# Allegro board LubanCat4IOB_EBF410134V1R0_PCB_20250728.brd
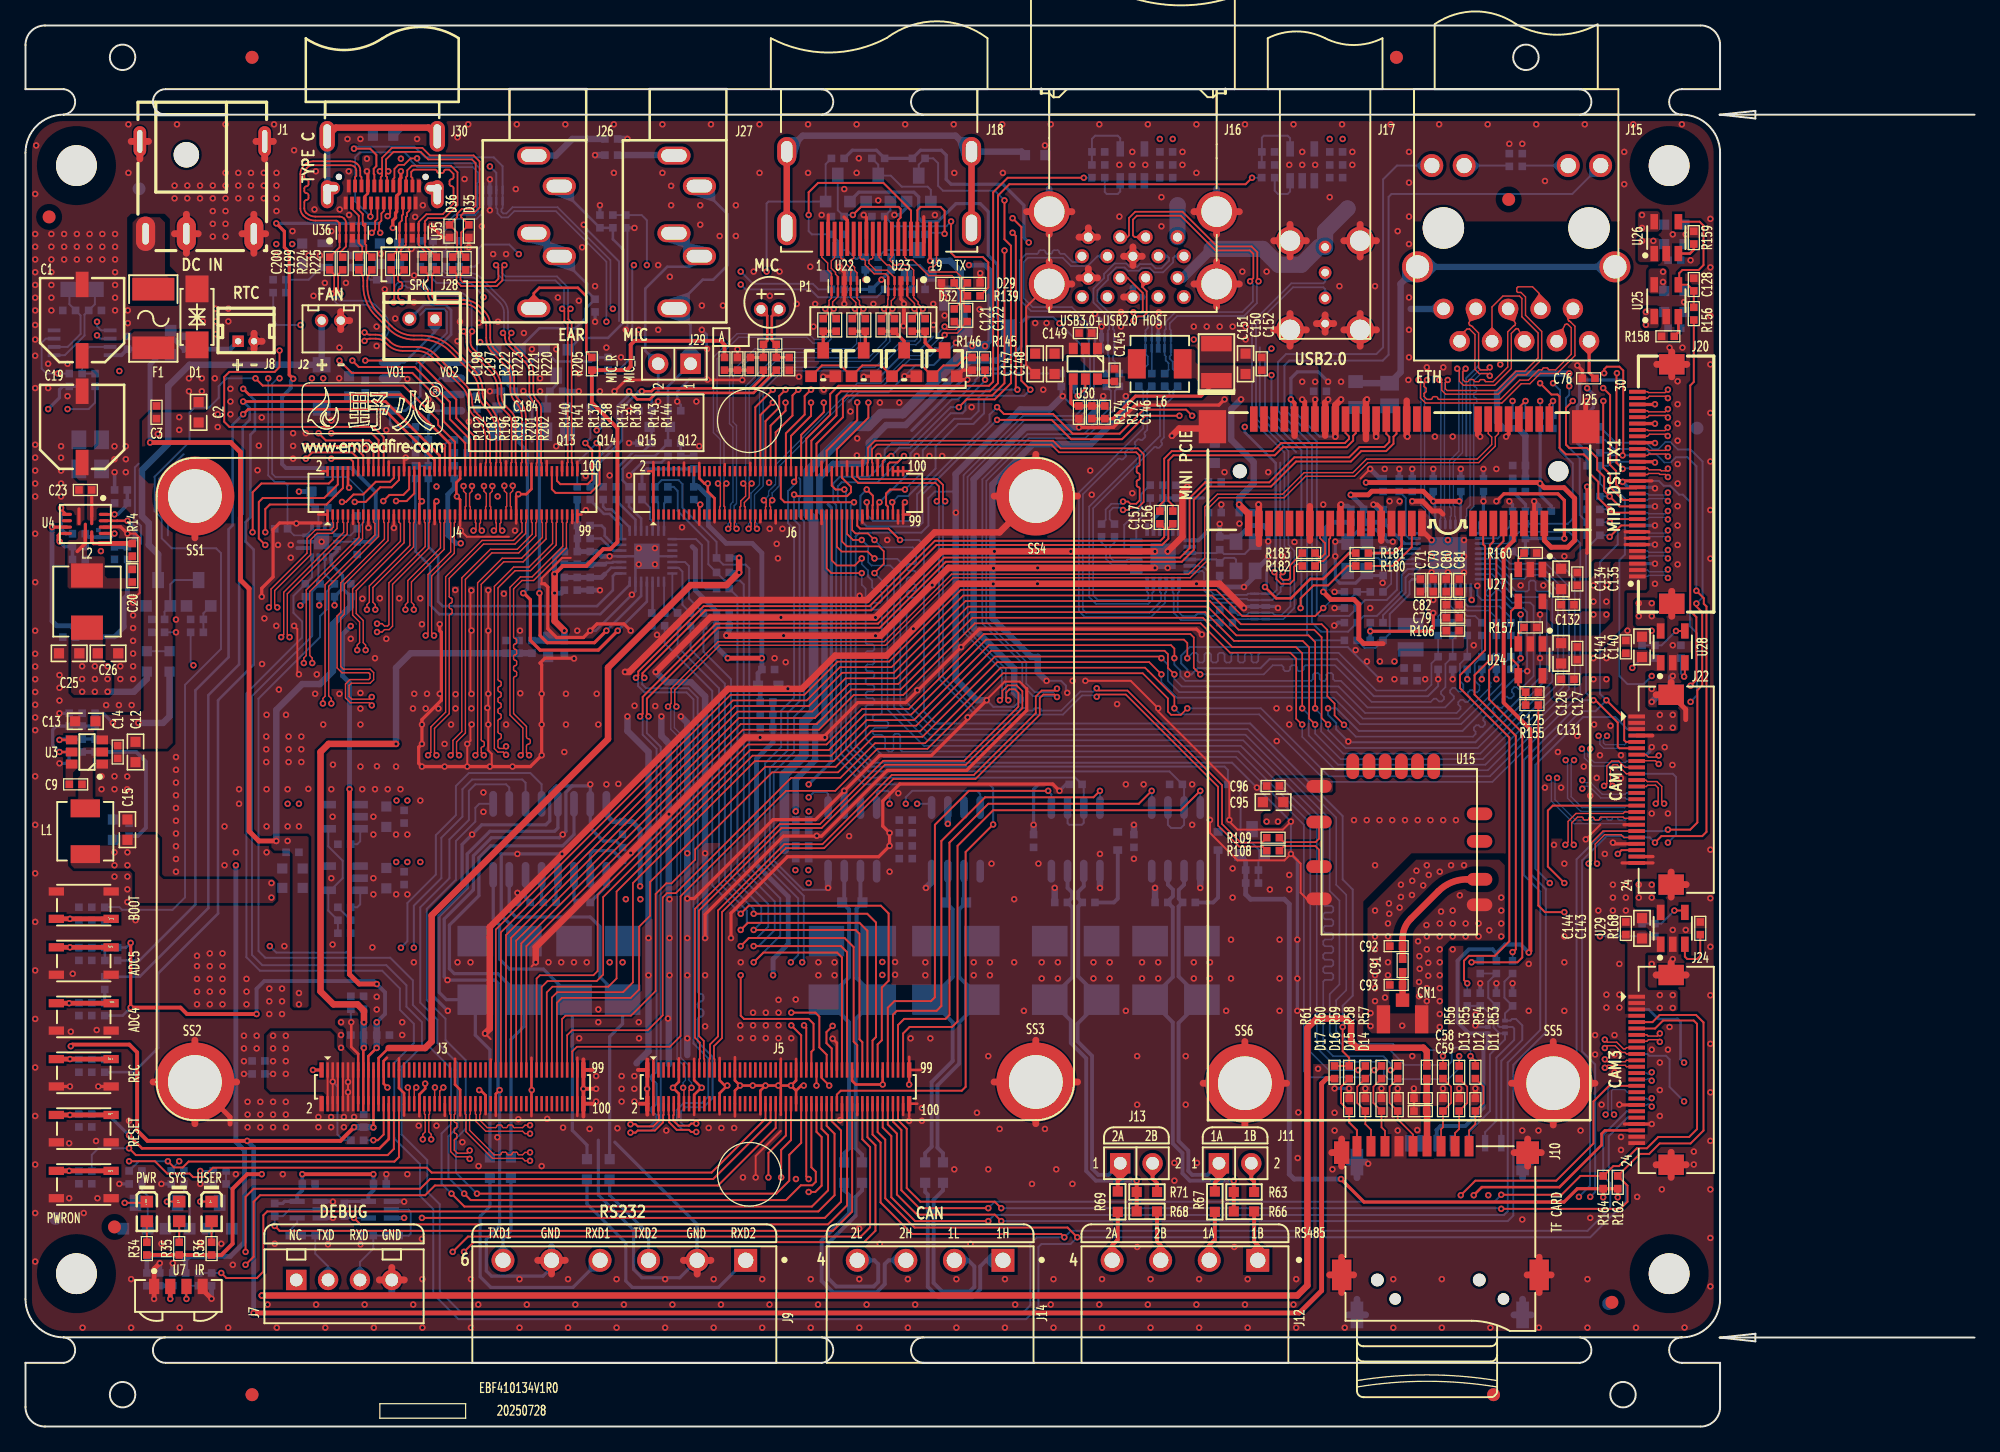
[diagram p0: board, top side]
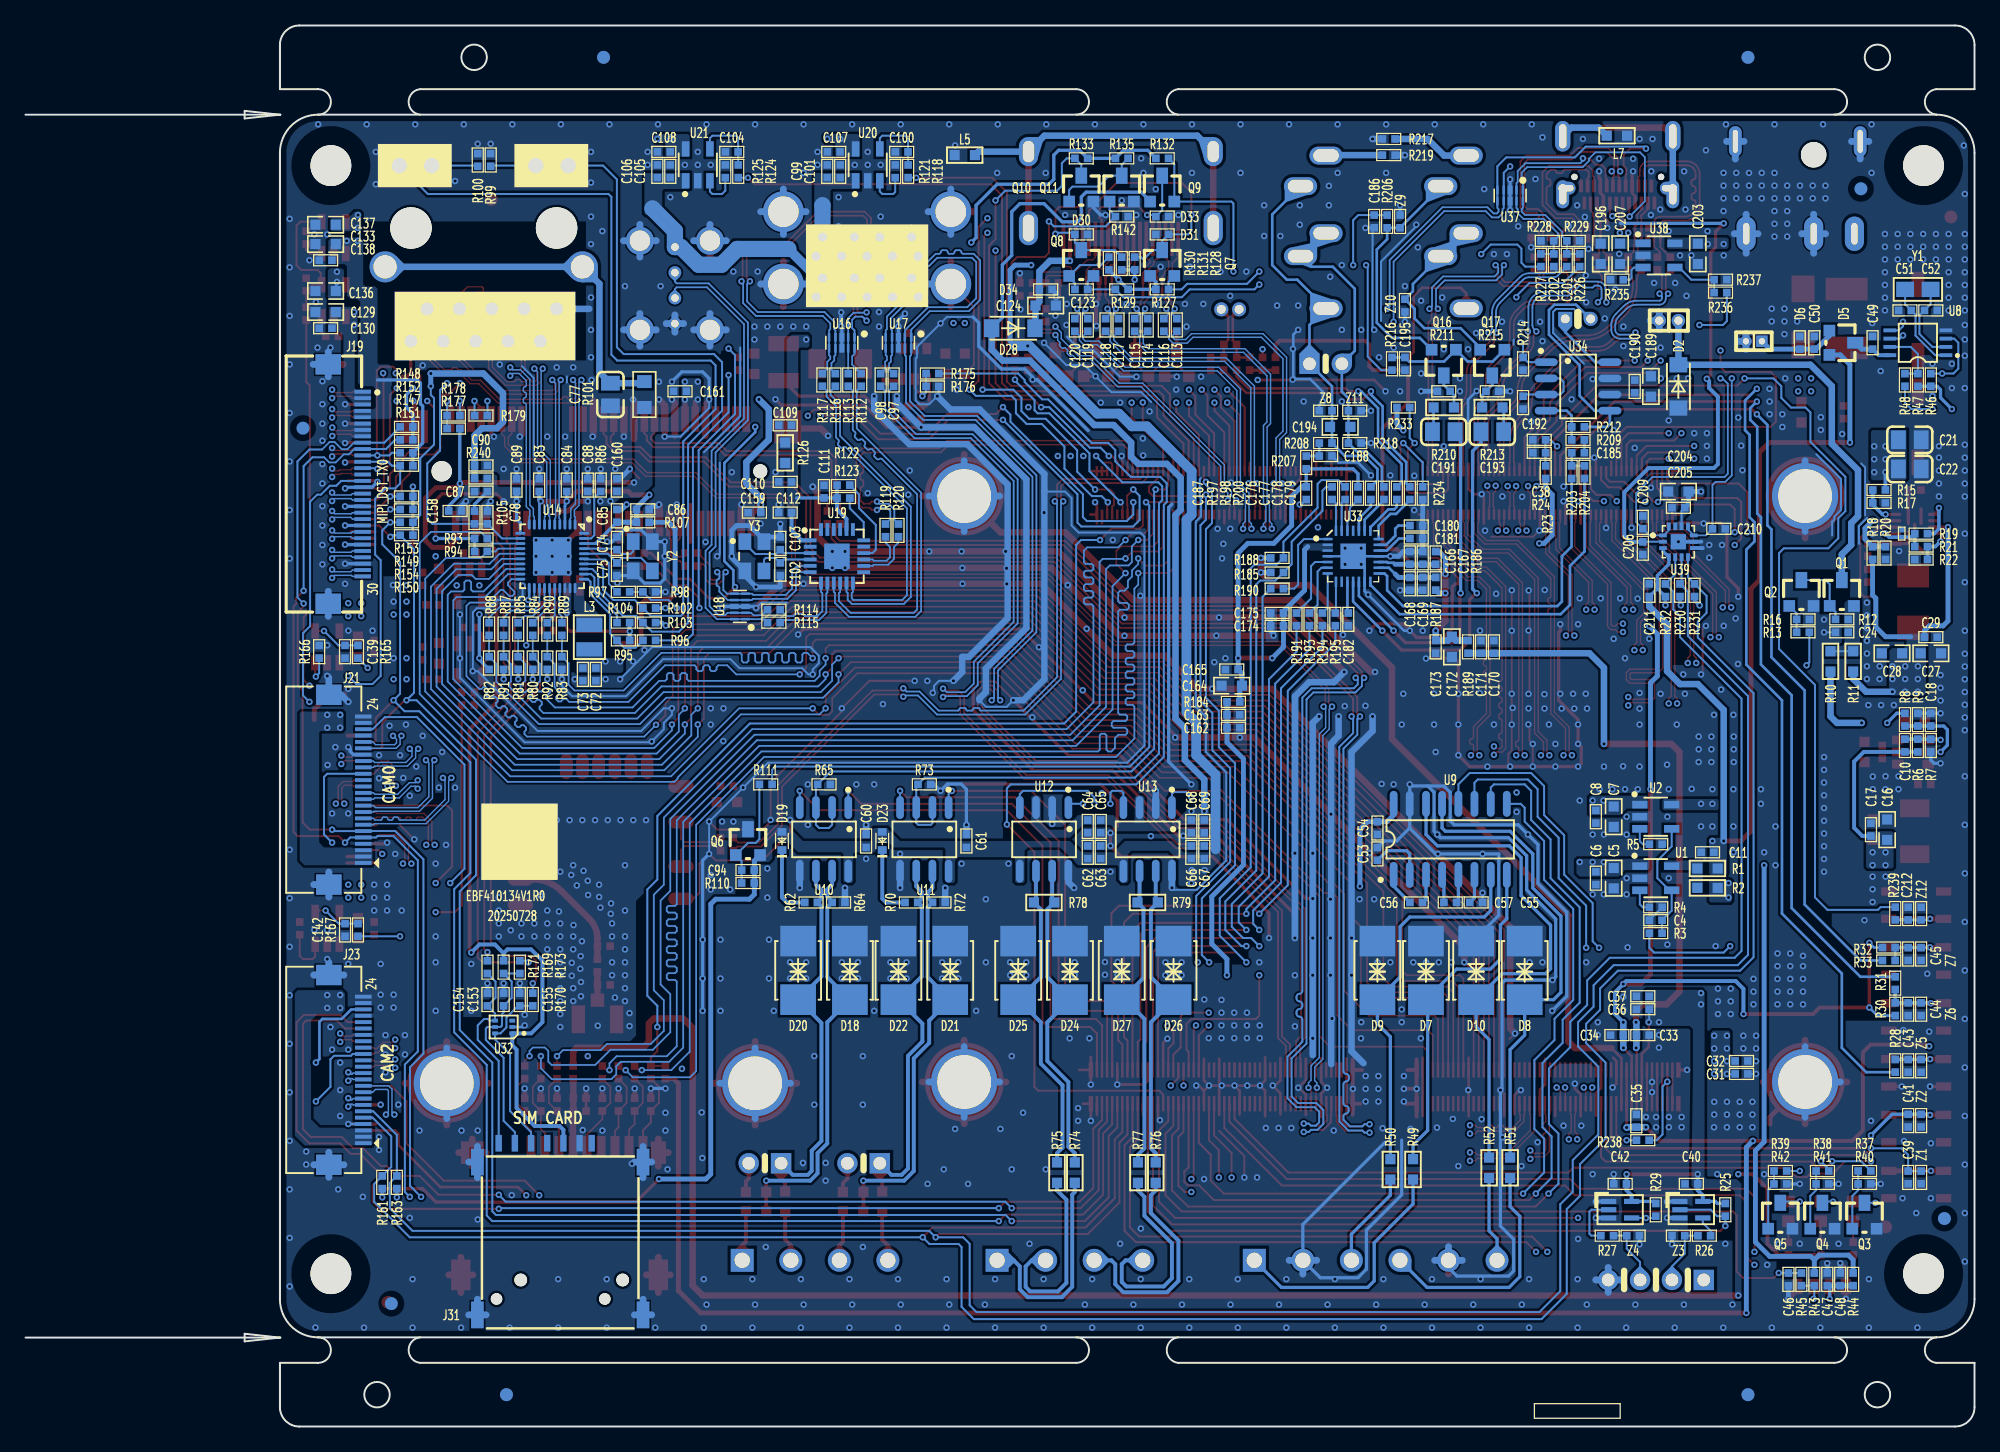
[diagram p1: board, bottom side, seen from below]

Outline 152.97 x 110 mm; copper layers: TOP, GND02, ART03, PWR04, GND05, BOTTOM. Coordinates in mm from the lower left corner of the outline.
Outline path: circle c7.62,107.5 r1 ; circle c7.62,2.5 r1 ; circle c117.76,107.5 r1 ; circle c125.38,2.5 r1 ; 3,105 0,105 0,108.48 arc(0.45,109.55) 1.52,110 131.48,110 arc(132.55,109.55) 133,108.48 133,105 130,105 ; 3,5 0,5 0,1.52 arc(0.45,0.45) 1.52,0 131.48,0 arc(132.55,0.45) 133,1.52 133,5 130,5 ; 11,105 62.5,105 ; 11,5 62.5,5 ; 70.5,105 122,105 ; 70.5,5 122,5 ; 0,100 arc(0.88,102.12) 3,103 130,103 arc(132.12,102.12) 133,100 133,10 arc(132.12,7.88) 130,7 3,7 arc(0.88,7.88) 0,10 0,100

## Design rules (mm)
net group 50OHM: nets GMAC1_MDC GMAC1_MDIO
net group B_DM1: nets B_DM1 HUB_DM1
net group B_DM2: nets B_DM2 HUB_DM2
net group B_DM3: nets B_DM3 HUB_DM3
net group B_DP1: nets B_DP1 HUB_DP1
net group B_DP2: nets B_DP2 HUB_DP2
net group B_DP3: nets B_DP3 HUB_DP3
net group C_GMAC1_TX: nets GMAC1_TXCLK GMAC1_TXEN
net group DIFF85OHM: nets PCIE20_0_RXN PCIE20_0_RXP
net group DIFF90OHM: nets USB30_SSRXN USB30_SSRXP
net group DIFF_TYPEC_CC: nets TYPEC_CC1 TYPEC_CC2
net group GMAC1_INT: nets GMAC1_INT N15600826
net group GMAC1_MCLK_INOUT: nets GMAC1_MCLK_INOUT PHY1_CLKOUT125
net group GMAC1_RXCLK: nets GMAC1_RXCLK N15599549
net group GMAC1_RXD0: nets GMAC1_RXD0 N15599533
net group GMAC1_RXD1: nets GMAC1_RXD1 N15599537
net group GMAC1_RXD2: nets GMAC1_RXD2 N15599541
net group GMAC1_RXD3: nets GMAC1_RXD3 N15599545
net group GMAC1_RXDV_CRS: nets GMAC1_RXDV_CRS N15599553
net group HDMI_TX0_D0N: nets HDMI_TX0_D0N TX_D0N_PORT
net group HDMI_TX0_D0P: nets HDMI_TX0_D0P TX_D0P_PORT
net group HDMI_TX0_D1N: nets HDMI_TX0_D1N TX_D1N_PORT
net group HDMI_TX0_D1P: nets HDMI_TX0_D1P TX_D1P_PORT
net group HDMI_TX0_D2N: nets HDMI_TX0_D2N TX_D2N_PORT
net group HDMI_TX0_D2P: nets HDMI_TX0_D2P TX_D2P_PORT
net group HDMI_TX0_D3N: nets HDMI_TX0_D3N TX_D3N_PORT
net group HDMI_TX0_D3P: nets HDMI_TX0_D3P TX_D3P_PORT
net group HDMI_TX0_SBDN: nets HDMI_EARC- HDMI_TX0_SBDN
net group HDMI_TX0_SBDP: nets HDMI_EARC+ HDMI_TX0_SBDP
net group HUB_DM4: nets HUB_DM4 N18057251
net group HUB_DP4: nets HUB_DP4 N18057253
net group I2C7_SCL_M0_CODEC: nets I2C7_SCL_M0_CODEC N18312152
net group I2C7_SDA_M0_CODEC: nets I2C7_SDA_M0_CODEC N18312149
net group I2S0_LRCK: nets I2S0_LRCK N18312158
net group I2S0_MCLK: nets I2S0_MCLK N18312167
net group I2S0_SCLK: nets I2S0_SCLK N18312164
net group I2S0_SDI0: nets I2S0_SDI0 N18312155
net group I2S0_SDO0: nets I2S0_SDO0 N18312161
net group N18639570: nets N18639570 N18639588
net group OTG_DM: nets OTG_DM TYPEC0_OTG_DM
net group OTG_DP: nets OTG_DP TYPEC0_OTG_DP
net group PCIE20_0_TX: nets PCIE20_0_TXN PCIE20_0_TXP
net group PE_TX: nets PE_TXN PE_TXP
net group RS485_1_A: nets N17728858 RS485_1_A
net group SBU_1: nets SBU_1 TYPEC0_SBU1/DP0_AUXP
net group SBU_2: nets SBU_2 TYPEC0_SBU2/DP0_AUXN
net group SDMMC_CLK: nets N16793151 SDMMC_CLK
net group SDMMC_CMD: nets N16793153 SDMMC_CMD
net group SDMMC_D0: nets N16793149 SDMMC_D0
net group SDMMC_D1: nets N16793157 SDMMC_D1
net group SDMMC_D2: nets N16793147 SDMMC_D2
net group SDMMC_D3: nets N16793155 SDMMC_D3
net group SS_TXN: nets SS_TXN USB30_SSTXN
net group SS_TXP: nets SS_TXP USB30_SSTXP
net group SSRX_1N: nets SSRX_1N TYPEC0_SSRX1N/DP0_TX0N
net group SSRX_1P: nets SSRX_1P TYPEC0_SSRX1P/DP0_TX0P
net group SSRX_2N: nets SSRX_2N TYPEC0_SSRX2N/DP0_TX2N
net group SSRX_2P: nets SSRX_2P TYPEC0_SSRX2P/DP0_TX2P
net group SSTX_1N: nets SSTX_1N TYPEC0_SSTX1N/DP0_TX1N
net group SSTX_1P: nets SSTX_1P TYPEC0_SSTX1P/DP0_TX1P
net group SSTX_2N: nets SSTX_2N TYPEC0_SSTX2N/DP0_TX3N
net group SSTX_2P: nets SSTX_2P TYPEC0_SSTX2P/DP0_TX3P
net group TXD2_232: nets N18528088 TXD2_232
net group USB20_HOST0_DM: nets N17770942 USB20_HOST0_DM
net group USB20_HOST0_DP: nets N17770939 USB20_HOST0_DP
net group USB20_HOST1_DM: nets N18057325 USB20_HOST1_DM
net group USB20_HOST1_DP: nets N18057335 USB20_HOST1_DP
net group 3W: nets CAM0_NRST CAM1_NRST CAM2_NRST CAM3_NRST CTP0_RST CTP1_RST FAN_PWM GMAC1_RSTN LCD0_RST LCD1_RST PCIE20X1_2_PERSTN_M0 RTC_32K_IN
net group C_ANLOG: nets MIC1_L MIC1_R MIC2_L MIC2_R N18315822 N18315825 N18315828 N18315831 N18479761 N18479774 N18639472 N18639500 N18645225 N18645232 N18645288 N18645295 OUT1_L OUT1_R OUT2_L OUT2_R
net group C_EARTH: nets N15752445 N18241743 N18479746 N18480944
net group C_MIPI_CSIO_RX: nets MIPI_CSI0_RX_CLK1N MIPI_CSI0_RX_CLK1P MIPI_CSI0_RX_D2N MIPI_CSI0_RX_D2P MIPI_CSI0_RX_D3N MIPI_CSI0_RX_D3P
net group C_MIPI_CSIO_RX_D1-2: nets MIPI_CSI0_RX_CLK0N MIPI_CSI0_RX_CLK0P MIPI_CSI0_RX_D0N MIPI_CSI0_RX_D0P MIPI_CSI0_RX_D1N MIPI_CSI0_RX_D1P
net group C_MIPI_DPHY0_RX: nets MIPI_DPHY0_RX_CLKN MIPI_DPHY0_RX_CLKP MIPI_DPHY0_RX_D1N MIPI_DPHY0_RX_D1P MIPI_DPHY0_RX_D2N MIPI_DPHY0_RX_D2P MIPI_DPHY0_RX_D3N MIPI_DPHY0_RX_D3P
net group C_MIPI_DPHY0_TX: nets MIPI_DPHY0_TX_CLKN MIPI_DPHY0_TX_CLKP MIPI_DPHY0_TX_D0N MIPI_DPHY0_TX_D0P MIPI_DPHY0_TX_D1N MIPI_DPHY0_TX_D1P MIPI_DPHY0_TX_D2N MIPI_DPHY0_TX_D2P
net group C_MIPI_DPHY1_RX: nets MIPI_DPHY1_RX_D1N MIPI_DPHY1_RX_D1P MIPI_DPHY1_RX_D3N MIPI_DPHY1_RX_D3P
net group C_MIPI_DPHY1_TX: nets MIPI_DPHY1_TX_CLKN MIPI_DPHY1_TX_CLKP MIPI_DPHY1_TX_D0N MIPI_DPHY1_TX_D0P MIPI_DPHY1_TX_D1N MIPI_DPHY1_TX_D1P MIPI_DPHY1_TX_D2N MIPI_DPHY1_TX_D2P MIPI_DPHY1_TX_D3N MIPI_DPHY1_TX_D3P
net group C_POWER: nets 1V05_AVDD_PHY HDMI_5V N18464854 SIM_VDD VCC_1V8_S0 VCC_3V3_SD VCCA3V3_CODEC VCCA_1V8_S0 VCCA_3V3_S0
net group DIFF100HOM: nets MDIN0_PHY MDIN1_PHY MDIN2_PHY MDIN3_PHY MDIP0_PHY MDIP1_PHY MDIP2_PHY MDIP3_PHY PCIE20_0_CLKN PCIE20_0_CLKP
net group MINIPCIE_3V3: nets N17592172
net group RS485_1_B: nets N17702231 N18804334 RS485_1_B
net group RTC_INT: nets N16793300 N18642319 RTC_INT SDMMC_DET VCC_1V8_S3

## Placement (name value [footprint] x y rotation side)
C1  220uF  [EC6P3]  4.45 86.87 180 top
C2  4.7uF  [C0603]  13.59 79.63 270 top
C3  0.1uF  [C0402]  10.29 79.63 270 top
C4  0.1uF  [C0402]  25.02 39.75 0 bottom
C5  10uF  [C0603]  28.32 43.05 270 bottom
C6  0.1uF  [C0402]  29.72 43.05 270 bottom
C7  10uF  [C0603]  28.32 47.88 270 bottom
C8  0.1uF  [C0402]  29.72 47.88 270 bottom
C9  0.1uF  [C0402]  3.94 50.42 0 top
C10  NC  [C0402]  5.46 53.47 90 bottom
C11  0.1uF  [C0402]  20.95 45.08 0 bottom
C12  10uF  [C0603]  8.64 52.96 270 top
C13  10uF  [C0603]  4.7 55.37 180 top
C14  0.1uF  [C0402]  7.24 52.96 270 top
C15  22uF  [C0603]  8 46.86 90 top
C16  22uF  [C0603]  6.86 46.86 90 bottom
C17  0.1uF  [C0402]  8.13 46.86 90 bottom
C18  NC  [C0402]  3.43 55.5 270 bottom
C19  220uF  [EC6P3]  4.45 78.48 180 top
C20  0.22uF  [C0402]  8.38 66.8 270 top
C21  22uF  [C0805]  5.08 77.47 180 bottom
C22  22uF  [C0805]  5.08 75.18 180 bottom
C23  0.1uF  [C0402]  4.7 73.53 180 top
C24  0.1uF  [C0402]  10.41 62.36 0 bottom
C25  22uF  [C0603]  3.43 60.7 180 top
C26  22uF  [C0603]  6.48 60.7 0 top
C27  22uF  [C0603]  3.43 60.7 180 bottom
C28  22uF  [C0603]  6.48 60.7 0 bottom
C29  0.1uF  [C0402]  3.43 61.97 180 bottom
C30  1uF  [C0201]  5.71 70.1 90 bottom
C31  0.1uF  [C0402]  18.29 27.68 180 bottom
C32  0.1uF  [C0402]  18.29 28.7 180 bottom
C33  0.1uF  [C0402]  26.04 30.73 180 bottom
C34  0.1uF  [C0402]  28.07 30.73 0 bottom
C35  0.1uF  [C0402]  26.54 24 90 bottom
C36  0.1uF  [C0402]  26.04 32.76 0 bottom
C37  0.1uF  [C0402]  26.04 33.78 0 bottom
C38  0.1uF  [C0402]  34.16 77.47 0 bottom
C39  0.1uF  [C0402]  5.21 19.56 270 bottom
C40  0.1uF  [C0402]  22.23 19.05 0 bottom
C41  0.1uF  [C0402]  5.21 24.02 270 bottom
C42  0.1uF  [C0402]  27.81 19.05 0 bottom
C43  10nF  [C0402]  5.21 28.32 270 bottom
C44  10nF  [C0402]  5.21 32.76 270 bottom
C45  10nF  [C0402]  5.21 37.1 270 bottom
C46  NC  [C0402]  14.61 11.56 270 bottom
C47  0.1uF  [C0402]  11.56 11.56 90 bottom
C48  1uF  [C0402]  10.54 11.56 90 bottom
C49  1uF  [C0402]  8 85.09 90 bottom
C50  0.1uF  [C0402]  12.57 85.09 90 bottom
C51  18pF  [C0402]  5.46 87.63 0 bottom
C52  18pF  [C0402]  3.43 87.63 180 bottom
C53  0.1uF  [C0402]  46.86 44.96 90 bottom
C54  4.7uF  [C0402]  46.86 46.99 270 bottom
C55  0.1uF  [C0402]  39.12 41.15 180 bottom
C56  0.1uF  [C0402]  43.81 41.15 0 bottom
C57  0.1uF  [C0402]  41.15 41.15 0 bottom
C58  4.7uF  [C0402]  109.47 25.78 180 top
C59  0.1uF  [C0402]  109.47 24.76 180 top
C60  0.1uF  [C0402]  87 45.97 90 bottom
C61  0.1uF  [C0402]  79.12 45.97 90 bottom
C62  4.7uF  [C0402]  69.6 45.08 90 bottom
C63  0.1uF  [C0402]  68.58 45.08 90 bottom
C64  4.7uF  [C0402]  69.6 47.12 270 bottom
C65  0.1uF  [C0402]  68.58 47.12 270 bottom
C66  4.7uF  [C0402]  61.47 45.08 90 bottom
C67  0.1uF  [C0402]  60.45 45.08 90 bottom
C68  4.7uF  [C0402]  61.47 47.12 270 bottom
C69  0.1uF  [C0402]  60.45 47.12 270 bottom
C70  0.1uF  [C0402]  110.49 66.04 90 top
C71  4.7uF  [C0402]  109.47 66.04 90 top
C72  4.7uF  [C0402]  108.2 59.05 270 bottom
C73  4.7uF  [C0402]  109.22 59.05 270 bottom
C74  18pF  [C0402]  106.55 69.34 90 bottom
C75  18pF  [C0402]  106.55 67.31 270 bottom
C76  0.1uF  [C0402]  122.68 82.29 180 top
C77  1nF  [C0805]  107.06 81.02 270 bottom
C78  0.1uF  [C0402]  116.71 71.37 90 bottom
C79  4.7uF  [C0402]  112.01 63.5 0 top
C80  0.1uF  [C0402]  111.51 66.04 90 top
C81  0.1uF  [C0402]  112.52 66.04 90 top
C82  4.7uF  [C0402]  112.01 64.51 0 top
C83  0.1uF  [C0402]  112.65 73.91 90 bottom
C84  0.1uF  [C0402]  110.49 73.91 90 bottom
C85  0.1uF  [C0402]  106.55 71.5 90 bottom
C86  4.7uF  [C0402]  104.52 72.01 180 bottom
C87  4.7uF  [C0402]  117.22 73.4 0 bottom
C88  0.1uF  [C0402]  108.84 73.91 90 bottom
C89  0.1uF  [C0402]  114.43 73.91 90 bottom
C90  0.1uF  [C0402]  117.22 75.45 180 bottom
C91  10pF  [C0402]  108.09 36.19 270 top
C92  NC  [C0402]  107.58 37.72 180 top
C93  NC  [C0402]  107.58 34.67 180 top
C94  0.1uF  [C0402]  96.27 43.69 0 bottom
C95  10uF  [C0603]  97.92 49.02 180 top
C96  0.1uF  [C0402]  97.92 50.29 180 top
C97  0.1uF  [C0402]  84.84 82.17 270 bottom
C98  0.1uF  [C0402]  85.85 82.17 270 bottom
C99  0.1uF  [C0402]  90.04 98.55 90 bottom
C100  0.1uF  [C0402]  84.2 100.07 0 bottom
C101  10uF  [C0402]  89.03 98.55 90 bottom
C102  NC  [C0402]  93.73 67.31 90 bottom
C103  NC  [C0402]  93.73 69.34 90 bottom
C104  0.1uF  [C0402]  97.54 100.07 0 bottom
C105  10uF  [C0402]  102.36 98.55 90 bottom
C106  0.1uF  [C0402]  103.38 98.55 90 bottom
C107  0.1uF  [C0402]  89.53 100.07 0 bottom
C108  0.1uF  [C0402]  102.87 100.07 0 bottom
C109  0.1uF  [C0402]  93.34 78.61 0 bottom
C110  4.7uF  [C0402]  93.34 74.17 0 bottom
C111  0.1uF  [C0402]  90.3 73.4 90 bottom
C112  0.1uF  [C0402]  93.34 71.75 0 bottom
C113  0.22uF  [C0402]  62.61 86.49 90 bottom
C114  0.22uF  [C0402]  64.9 86.49 90 bottom
C115  0.22uF  [C0402]  65.91 86.49 90 bottom
C116  0.22uF  [C0402]  63.63 86.49 90 bottom
C117  0.22uF  [C0402]  67.18 86.49 90 bottom
C118  0.22uF  [C0402]  68.2 86.49 90 bottom
C119  0.22uF  [C0402]  69.6 86.49 90 bottom
C120  0.22uF  [C0402]  70.61 86.49 90 bottom
C121  1uF  [C0402]  72.9 87.25 90 top
C122  1uF  [C0402]  73.91 87.25 90 top
C123  100pF  [C0402]  70.1 89.28 180 bottom
C124  1uF  [C0603]  72.9 88.01 180 bottom
C125  0.1uF  [C0402]  118.24 57.66 0 top
C126  10uF  [C0603]  120.52 60.7 270 top
C127  0.1uF  [C0402]  121.79 60.7 270 top
C128  0.1uF  [C0402]  130.94 89.66 90 top
C129  10uF  [C0603]  129.41 87.5 0 bottom
C130  0.1uF  [C0402]  129.41 86.23 0 bottom
C131  0.1uF  [C0402]  121.03 58.67 0 top
C132  0.1uF  [C0402]  121.03 64.51 0 top
C133  10uF  [C0603]  129.41 92.84 0 bottom
C134  10uF  [C0603]  120.52 66.55 270 top
C135  0.1uF  [C0402]  121.79 66.55 270 top
C136  10uF  [C0603]  129.41 89.15 0 bottom
C137  10uF  [C0603]  129.41 94.36 0 bottom
C138  0.1uF  [C0402]  129.41 91.57 0 bottom
C139  0.1uF  [C0402]  127.89 60.83 270 bottom
C140  10uF  [C0603]  126.87 61.21 90 top
C141  0.1uF  [C0402]  125.6 61.21 90 top
C142  0.1uF  [C0402]  127.89 38.99 270 bottom
C143  10uF  [C0603]  126.87 39.11 90 top
C144  0.1uF  [C0402]  125.6 39.11 90 top
C145  0.1uF  [C0402]  85.47 82.55 90 top
C146  NC  [C0402]  84.71 79.63 90 top
C147  10uF  [C0603]  79.25 83.44 270 top
C148  10uF  [C0603]  80.77 83.44 270 top
C149  0.1uF  [C0402]  83.19 85.85 0 top
C150  22uF  [C0603]  95.76 83.44 90 top
C151  220uF  [CASE-B_3528]  93.47 83.56 90 top
C152  0.1uF  [C0402]  97.03 83.44 90 top
C153  33pF  [C0402]  115.44 33.53 90 bottom
C154  33pF  [C0402]  116.71 33.53 90 bottom
C155  33pF  [C0402]  114.17 33.53 90 bottom
C156  0.1uF  [C0402]  90.04 71.37 90 top
C157  0.1uF  [C0402]  89.03 71.37 90 top
C158  0.1uF  [C0402]  119.25 71.88 180 bottom
C159  0.1uF  [C0402]  95.76 71.75 0 bottom
C160  4.7uF  [C0402]  106.55 73.91 90 bottom
C161  4.7uF  [C0402]  101.6 81.28 0 bottom
C162  4.7uF  [C0402]  58.17 54.86 180 bottom
C163  0.1uF  [C0402]  58.17 55.88 180 bottom
C164  10uF  [C0603]  58.29 58.16 0 bottom
C165  0.1uF  [C0402]  58.29 59.43 0 bottom
C166  0.1uF  [C0402]  44.32 68.2 90 bottom
C167  4.7uF  [C0402]  43.31 68.2 90 bottom
C168  0.1uF  [C0402]  44.32 66.17 270 bottom
C169  4.7uF  [C0402]  43.31 66.17 270 bottom
C170  4.7uF  [C0402]  37.72 61.21 90 bottom
C171  0.1uF  [C0402]  38.73 61.21 90 bottom
C172  10uF  [C0603]  41.02 61.21 270 bottom
C173  0.1uF  [C0402]  42.29 61.21 270 bottom
C174  1uF  [C0402]  54.74 62.86 0 bottom
C175  0.1uF  [C0402]  54.74 63.88 0 bottom
C176  1uF  [C0402]  47.37 73.28 90 bottom
C177  1uF  [C0402]  46.35 73.28 90 bottom
C178  1uF  [C0402]  45.34 73.28 90 bottom
C179  1uF  [C0402]  44.32 73.28 90 bottom
C180  10uF  [C0402]  43.81 70.74 180 bottom
C181  10uF  [C0402]  43.81 69.72 180 bottom
C182  10uF  [C0402]  49.15 63.37 270 bottom
C183  4.7uF  [C0402]  55.88 83.44 90 top
C184  100pF  [C0402]  58.42 84.96 0 top
C185  0.22uF  [C0402]  31.11 76.45 180 bottom
C186  1uF  [C0402]  47.12 94.61 270 bottom
C187  0.1uF  [C0402]  52.45 73.28 270 bottom
C188  1uF  [C0402]  50.93 76.2 180 bottom
C189  22uF  [C0603]  25.4 81.66 90 bottom
C190  0.1uF  [C0402]  26.67 81.66 90 bottom
C191  47uF  [C0805]  41.66 78.1 0 bottom
C192  1uF  [C0402]  35.43 80.39 270 bottom
C193  47uF  [C0805]  37.85 78.1 180 bottom
C194  100pF  [C0603]  49.78 78.48 180 bottom
C195  0.1uF  [C0402]  44.7 83.44 270 bottom
C196  10uF  [C0603]  29.34 92.07 270 bottom
C197  0.1uF  [C0402]  29.72 91.31 270 top
C198  0.1uF  [C0402]  28.7 91.31 270 top
C199  0.1uF  [C0402]  24.89 91.31 270 top
C200  0.1uF  [C0402]  23.88 91.31 270 top
C201  0.1uF  [C0402]  32 91.57 270 bottom
C202  0.1uF  [C0402]  33.02 91.57 270 bottom
C203  10uF  [C0603]  21.72 92.07 270 bottom
C204  10uF  [C0603]  23.24 73.4 0 bottom
C205  0.1uF  [C0402]  23.24 72.13 0 bottom
C206  0.1uF  [C0402]  26.04 68.96 270 bottom
C207  10uF  [C0603]  27.81 92.07 270 bottom
C209  220pF  [C0402]  26.04 70.99 90 bottom
C210  220pF  [C0402]  20.07 70.48 180 bottom
C211  1uF  [C0402]  25.53 65.66 90 bottom
C212  10nF  [C0402]  5.21 40.27 90 bottom
CN1  WiFi-Ant  [UFL-3]  108.08 31.97 180 top
D1  SMAJ13CA  [SMA_CA]  13.46 87.12 270 top
D2  1N4148W  [SOD-123]  23.24 81.66 90 bottom
D3  GREEN  [LED0603]  12.06 16.89 90 top
D4  GREEN  [LED0603]  14.61 16.89 90 top
D5  BAT54C  [SOT23]  10.4 85.09 270 bottom
D6  KLXES15AAA1  [ES0402]  13.72 85.09 270 bottom
D7  SMBJ15CA  [SMB-CA]  43.05 35.81 270 bottom
D8  SMBJ15CA  [SMB-CA]  35.31 35.81 270 bottom
D9  SMBJ15CA  [SMB-CA]  46.86 35.81 270 bottom
D10  SMBJ15CA  [SMB-CA]  39.12 35.81 270 bottom
D11  KLXES15AAA1  [ES0402]  113.79 25.27 270 top
D12  KLXES15AAA1  [ES0402]  112.52 25.27 270 top
D13  KLXES15AAA1  [ES0402]  111.25 25.27 270 top
D14  KLXES15AAA1  [ES0402]  107.7 25.27 270 top
D15  KLXES15AAA1  [ES0402]  106.43 25.27 270 top
D16  KLXES15AAA1  [ES0402]  105.16 25.27 270 top
D17  KLXES15AAA1  [ES0402]  103.89 25.27 270 top
D18  SMBJ6.5CA  [SMB-CA]  88.27 35.81 270 bottom
D19  RB521S-30  [SOD523]  93.6 45.97 90 bottom
D20  SMBJ6.5CA  [SMB-CA]  92.33 35.81 270 bottom
D21  SMBJ6.5CA  [SMB-CA]  80.39 35.81 270 bottom
D22  SMBJ6.5CA  [SMB-CA]  84.45 35.81 270 bottom
D23  RB521S-30  [SOD523]  85.72 45.97 90 bottom
D24  SMBJ6.5CA  [SMB-CA]  70.99 35.81 270 bottom
D25  SMBJ6.5CA  [SMB-CA]  75.06 35.81 270 bottom
D26  SMBJ6.5CA  [SMB-CA]  62.87 35.81 270 bottom
D27  SMBJ6.5CA  [SMB-CA]  66.93 35.81 270 bottom
D28  1N5819W  [SOD-123]  75.44 86.23 180 bottom
D29  KLXES15AAA1  [ES0402]  74.42 89.79 180 top
D30  KLXES15AAA1  [ES0402]  70.1 93.6 0 bottom
D31  KLXES15AAA1  [ES0402]  63.75 93.6 180 bottom
D32  KLXES15AAA1  [ES0402]  72.39 89.79 0 top
D33  KLXES15AAA1  [ES0402]  63.75 94.99 0 bottom
D34  KLXES15AAA1  [ES0402]  72.9 89.28 0 bottom
D35  KLXES15AAA1  [ES0402]  34.8 93.85 270 top
D36  KLXES15AAA1  [ES0402]  33.27 93.85 270 top
F1  SMD1812P200TF16  [F1812]  10.03 86.99 270 top
H1  -  [NPTH_M3]  4 99 0 top
H2  -  [NPTH_M3]  4 12 0 top
H3  -  [NPTH_M3]  129 12 0 top
H4  -  [NPTH_M3]  129 99 0 top
J1  DC-044A-20A  [DC_IN_TH_3P_10R1X11R6]  13.88 98.15 270 top
J2  A1501WV-2P  [ZH1P5MM_TH_2P]  23.99 86.83 0 top
J3  DF40C-100DP-0.4V(51)  [DF40C-100DP-0P4V]  33.51 26.67 0 top
J4  DF40C-100DS-0.4V(51)  [DF40HC-100DS-0P4V]  33.51 73.31 0 top
J5  DF40C-100DP-0.4V(51)  [DF40C-100DP-0P4V]  59.08 26.67 0 top
J6  DF40C-100DS-0.4V(51)  [DF40HC-100DS-0P4V]  59.08 73.31 0 top
J7  XH-4A  [XH2R54-4P-V]  25 11.51 0 top
J8  1.25T-2A  [GH1P25_TH_2P]  17.31 85.21 0 top
J9  CON6  [DB2ERC-3P81-6P]  47 13.05 180 top
J10  TF_Card  [TFCARD]  110.1 11.5 0 top
J11  -  [HDR1X2-2R54-TM-VM]  94.94 20.67 0 top
J12  WJ15EDGRC-3.81-4P  [DB2ERC-3P81-4P]  91 13.05 180 top
J13  -  [HDR1X2-2R54-TM-VM]  87.19 20.67 0 top
J14  WJ15EDGRC-3.81-4P  [DB2ERC-3P81-4P]  71 13.05 180 top
J15  -  [HY911130A]  117 94.1 0 top
J16  USB3D0_USB2D0-A-D  [USB3D0-AF-18P]  86.92 91.88 180 top
J17  USB_AF  [USB-AF]  102 89.6 0 top
J18  A111926-A-05-R  [CON_RA_HDMI_19P_0P5_SM]  67 98.62 180 top
J19  FPC_0R5_30P_D  [FPC-30P-0P5]  127.86 73.99 270 bottom
J20  FPC_0R5_30P_D  [FPC-30P-0P5]  127.86 73.99 90 top
J21  FPC_0P5_24P_D  [FPC_24P_0P5]  127.81 50 90 bottom
J22  FPC_0P5_24P_D  [FPC_24P_0P5]  127.81 50 270 top
J23  FPC_0P5_24P_D  [FPC_24P_0P5]  127.81 28 90 bottom
J24  FPC_0P5_24P_D  [FPC_24P_0P5]  127.81 28 270 top
J25  MINI-PCIE  [PCIE_52P]  107.8 75 180 top
J26  PJ-325C5-G  [EAR_JACK]  40.8 93.69 270 top
J27  PJ-325C5-R  [EAR_JACK]  51.8 93.69 270 top
J28  PH-2A  [PH-1X2-2P0_L]  31.13 86.97 180 top
J29  -  [HDR1X2-2R54-TM-VM]  50.93 83.44 180 top
J30  TYPE-C  [USB-C-SMD_TYC-324G]  28 98.68 180 top
J31  SIM-7-1  [NANO_SIM]  111 15.5 180 bottom
L1  3.3uH  [L4520]  4.7 46.74 270 top
L2  1.5uH  [L0518]  4.83 64.77 270 top
L3  2.2uH  [L2520]  108.71 61.97 270 bottom
L5  330R 100MHz  [L0603]  79.25 99.82 0 bottom
L6  3.3uH  [L4520]  89.02 83.44 0 top
L7  330R 100MHz  [L0603]  28.07 101.34 180 bottom
LED1  RED  [LED0603]  9.53 16.89 90 top
NOREF  -  []  66.5 104 0 top
NOREF#2  -  [unnamed#2]  17.78 107.5 0 top
NOREF#3  -  []  114.55 50.18 0 top
NOREF#4  -  [unnamed#2]  1.85 94.97 0 top
NOREF#5  -  [unnamed#2]  115.22 2.5 0 top
NOREF#6  -  [unnamed#2]  116.41 96.34 0 top
NOREF#7  -  []  7 104 0 top
NOREF#8  -  []  0 41 0 top
NOREF#9  -  []  7 6 0 top
NOREF#10  -  [unnamed#2]  124.51 9.75 0 top
NOREF#11  -  [unnamed#2]  107.6 107.5 0 top
NOREF#12  -  []  132.97 103 0 top
NOREF#13  -  []  126 6 0 top
NOREF#14  -  [unnamed#2]  6.99 15.67 0 top
NOREF#15  -  []  126 104 0 top
NOREF#16  -  []  132.97 6.98 0 top
NOREF#17  -  [unnamed#2]  17.78 2.5 0 top
NOREF#18  -  []  7 7 90 top
NOREF#19  -  []  66.5 6 0 top
NOREF#20  -  [unnamed#2]  17.78 2.5 180 bottom
NOREF#21  -  [unnamed#2]  124.26 9.65 180 bottom
NOREF#22  -  [unnamed#2]  107.6 107.5 180 bottom
NOREF#23  -  [unnamed#2]  2.36 16.33 180 bottom
NOREF#24  -  [unnamed#2]  8.92 97.18 180 bottom
NOREF#25  -  [unnamed#2]  131.19 78.38 180 bottom
NOREF#26  -  [unnamed#2]  115.22 2.5 180 bottom
NOREF#27  -  [unnamed#2]  17.78 107.5 180 bottom
P1  MIC_POM  [MIC2-4R00-TM]  58.42 87.71 0 top
Q1  AO3407  [SOT23]  10.41 65.42 180 bottom
Q2  SS8050  [SOT23]  13.59 65.42 180 bottom
Q3  SS8050  [SOT23]  8.64 16.52 180 bottom
Q4  SS8050  [SOT23]  11.94 16.52 180 bottom
Q5  SS8050  [SOT23]  15.24 16.52 180 bottom
Q6  AO3407  [SOT23]  96.27 45.86 180 bottom
Q7  2SK3018  [SOT23]  63.75 91.32 180 bottom
Q8  2SK3018  [SOT23]  70.1 91.32 180 bottom
Q9  2SK3018  [SOT23]  63.75 97.17 180 bottom
Q10  2SK3018  [SOT23]  70.1 97.17 180 bottom
Q11  2SK3018  [SOT23]  66.93 97.17 180 bottom
Q12  2SK3018  [SOT23]  72.14 83.45 0 top
Q13  2SK3018  [SOT23]  62.61 83.45 0 top
Q14  2SK3018  [SOT23]  65.79 83.45 0 top
Q15  2SK3018  [SOT23]  68.96 83.45 0 top
Q16  WNM2016-3/TR  [SOT23]  41.66 83.55 0 bottom
Q17  WNM2016-3/TR  [SOT23]  37.85 83.55 0 bottom
R1  0R  [R0603]  20.95 43.81 0 bottom
R2  NC  [R0603]  20.95 42.29 0 bottom
R3  1K  [R0402]  25.02 38.73 180 bottom
R4  3.4K  [R0402]  25.02 40.77 180 bottom
R5  6.8K  [R0402]  25.02 45.72 180 bottom
R6  100K  [R0402]  4.45 53.47 90 bottom
R7  30K  [R0402]  3.43 53.47 270 bottom
R8  140K  [R0402]  5.46 55.5 270 bottom
R9  20K  [R0402]  4.45 55.5 90 bottom
R10  NC  [R0603]  11.3 60.07 90 bottom
R11  0R  [R0603]  9.53 60.07 90 bottom
R12  20K  [R0402]  10.41 63.37 0 bottom
R13  1K  [R0402]  13.46 62.36 0 bottom
R14  3.3R  [R0402]  8.38 68.83 270 top
R15  140K  [R0402]  7.49 73.53 0 bottom
R16  10K  [R0402]  13.46 63.37 180 bottom
R17  20K  [R0402]  7.49 72.52 0 bottom
R18  75k  [R0402]  8 68.58 90 bottom
R19  100K  [R0402]  4.19 70.1 180 bottom
R20  10K  [R0402]  6.99 68.58 270 bottom
R21  100K  [R0402]  4.19 69.09 180 bottom
R22  NC  [R0402]  4.19 68.07 180 bottom
R23  25.5K  [R0402]  33.66 74.93 90 bottom
R24  10K  [R0402]  34.16 76.45 0 bottom
R25  10K  [R0402]  19.56 17.02 270 bottom
R26  560R  [R0402]  21.21 14.98 180 bottom
R27  560R  [R0402]  28.83 14.98 0 bottom
R28  100R  [R0402]  6.22 28.32 270 bottom
R29  10K  [R0402]  25.02 17.02 270 bottom
R30  10K  [R0402]  6.22 32.76 270 bottom
R31  100R  [R0402]  6.22 34.81 90 bottom
R32  10K  [R0402]  6.73 37.61 0 bottom
R33  100R  [R0402]  6.73 36.59 0 bottom
R34  4.7K  [R0402]  9.53 13.97 90 top
R35  10K  [R0402]  12.06 13.97 90 top
R36  10K  [R0402]  14.61 13.97 90 top
R37  4.7K  [R0402]  8.64 20.06 0 bottom
R38  1K  [R0402]  11.94 20.06 0 bottom
R39  1K  [R0402]  15.24 20.06 0 bottom
R40  10K  [R0402]  8.64 19.05 180 bottom
R41  10K  [R0402]  11.94 19.05 180 bottom
R42  10K  [R0402]  15.24 19.05 180 bottom
R43  10K  [R0402]  12.57 11.56 270 bottom
R44  22R  [R0402]  9.53 11.56 270 bottom
R45  22R  [R0402]  13.59 11.56 270 bottom
R46  10K  [R0402]  3.43 82.17 90 bottom
R47  10K  [R0402]  4.45 82.17 90 bottom
R48  22R  [R0402]  5.46 82.17 270 bottom
R49  0R  [R0603]  44.07 20.19 270 bottom
R50  0R  [R0603]  45.85 20.19 270 bottom
R51  0R  [R0603]  36.45 20.32 270 bottom
R52  0R  [R0603]  38.1 20.32 270 bottom
R53  22R  [R0402]  113.79 27.81 270 top
R54  22R  [R0402]  112.52 27.81 270 top
R55  22R  [R0402]  111.25 27.81 270 top
R56  0R  [R0402]  109.98 27.81 270 top
R57  22R  [R0402]  107.7 27.81 270 top
R58  22R  [R0402]  106.43 27.81 270 top
R59  22R  [R0402]  105.16 27.81 270 top
R60  100R  [R0402]  103.89 27.81 270 top
R61  10K  [R0402]  102.74 27.81 90 top
R62  4.7K  [R0402]  91.31 41.15 180 bottom
R63  120R  [R0603]  95.63 18.41 0 top
R64  4.7K  [R0402]  89.15 41.15 180 bottom
R65  10K  [R0402]  90.3 50.42 180 bottom
R66  0R  [R0603]  95.63 16.89 0 top
R67  0R  [R0603]  93.34 17.65 270 top
R68  0R  [R0603]  88.01 16.89 0 top
R69  0R  [R0603]  85.72 17.65 270 top
R70  4.7K  [R0402]  83.44 41.15 180 bottom
R71  120R  [R0603]  88.01 18.41 0 top
R72  4.7K  [R0402]  81.28 41.15 180 bottom
R73  10K  [R0402]  82.42 50.42 180 bottom
R74  0R  [R0603]  70.61 19.94 270 bottom
R75  0R  [R0603]  72.01 19.94 270 bottom
R76  0R  [R0603]  64.26 19.94 270 bottom
R77  0R  [R0603]  65.66 19.94 270 bottom
R78  120R  [R0603]  73.03 41.15 0 bottom
R79  120R  [R0603]  64.9 41.15 0 bottom
R80  4.7K  [R0402]  113.16 59.94 90 bottom
R81  4.7K  [R0402]  114.3 59.94 90 bottom
R82  4.7K  [R0402]  116.59 59.94 90 bottom
R83  4.7K  [R0402]  110.87 59.94 270 bottom
R84  22R  [R0402]  113.16 62.61 90 bottom
R85  22R  [R0402]  114.3 62.61 90 bottom
R86  2.49K  [R0402]  107.82 73.91 90 bottom
R87  22R  [R0402]  115.44 62.61 90 bottom
R88  22R  [R0402]  116.59 62.61 90 bottom
R89  22R  [R0402]  110.87 62.61 90 bottom
R90  22R  [R0402]  112.01 62.61 90 bottom
R91  4.7K  [R0402]  115.44 59.94 270 bottom
R92  4.7K  [R0402]  112.01 59.94 270 bottom
R93  4.7K  [R0402]  117.22 69.72 180 bottom
R94  4.7K  [R0402]  117.22 68.71 180 bottom
R95  4.7K  [R0402]  106.05 61.72 0 bottom
R96  NC  [R0402]  104.01 61.72 0 bottom
R97  0R  [R0402]  106.05 65.53 0 bottom
R98  NC  [R0402]  104.01 65.53 180 bottom
R99  510R  [R0402]  116.46 99.44 90 bottom
R100  510R  [R0402]  117.47 99.44 90 bottom
R101  1M  [R0805]  104.39 81.02 270 bottom
R102  4.7K  [R0402]  104.01 64.26 180 bottom
R103  4.7K  [R0402]  104.01 63.12 180 bottom
R104  4.7K  [R0402]  106.05 63.12 180 bottom
R105  4.7K  [R0402]  117.73 71.37 270 bottom
R106  0R  [R0402]  112.01 62.48 0 top
R107  0R  [R0402]  104.52 70.99 0 bottom
R108  2.2R  [R0402]  97.92 45.21 0 top
R109  2.2R  [R0402]  97.92 46.23 0 top
R110  10K  [R0402]  96.27 42.67 0 bottom
R111  560R  [R0402]  94.87 50.42 0 bottom
R112  2.2R  [R0402]  87.38 82.17 270 bottom
R113  2.2R  [R0402]  88.39 82.17 270 bottom
R114  2.2R  [R0402]  94.23 64.13 180 bottom
R115  2.2R  [R0402]  94.23 63.12 180 bottom
R116  2.2R  [R0402]  89.41 82.17 270 bottom
R117  2.2R  [R0402]  90.42 82.17 270 bottom
R118  1K  [R0402]  83.69 98.55 90 bottom
R119  2.2R  [R0402]  85.47 70.36 90 bottom
R120  2.2R  [R0402]  84.45 70.36 90 bottom
R121  3.4K  [R0402]  84.71 98.55 90 bottom
R122  100K  [R0402]  88.77 73.91 180 bottom
R123  100K  [R0402]  88.77 72.9 180 bottom
R124  1K  [R0402]  97.03 98.55 90 bottom
R125  3.4K  [R0402]  98.04 98.55 90 bottom
R126  0R  [R0603]  93.34 76.45 270 bottom
R127  10K  [R0402]  63.75 89.28 180 bottom
R128  2.2K  [R0402]  65.91 91.31 90 bottom
R129  10K  [R0402]  66.93 89.28 0 bottom
R130  1K  [R0402]  67.94 91.31 90 bottom
R131  2.2K  [R0402]  66.93 91.31 90 bottom
R132  27K  [R0402]  63.75 99.57 180 bottom
R133  47K  [R0402]  70.1 99.57 0 bottom
R134  499R  [R0402]  67.18 86.49 270 top
R135  47K  [R0402]  66.93 99.57 180 bottom
R136  499R  [R0402]  68.2 86.49 270 top
R137  499R  [R0402]  64.9 86.49 270 top
R138  499R  [R0402]  65.91 86.49 270 top
R139  1.2K  [R0402]  74.42 88.77 180 top
R140  499R  [R0402]  62.61 86.49 270 top
R141  499R  [R0402]  63.63 86.49 270 top
R142  47K  [R0402]  66.93 94.99 180 bottom
R143  499R  [R0402]  69.6 86.49 270 top
R144  499R  [R0402]  70.61 86.49 270 top
R145  1K  [R0402]  75.31 83.44 90 top
R146  10K  [R0402]  74.3 83.44 270 top
R147  10K  [R0402]  123.06 76.45 0 bottom
R148  10K  [R0402]  123.06 78.48 0 bottom
R149  10K  [R0402]  123.06 72.01 0 bottom
R150  10K  [R0402]  123.06 69.98 0 bottom
R151  10K  [R0402]  123.06 75.44 0 bottom
R152  10K  [R0402]  123.06 77.47 0 bottom
R153  10K  [R0402]  123.06 73.02 0 bottom
R154  10K  [R0402]  123.06 70.99 0 bottom
R155  1K  [R0402]  118.24 56.64 180 top
R156  1K  [R0402]  130.94 87.37 90 top
R157  6.8K  [R0402]  118.11 62.74 0 top
R158  6.8K  [R0402]  128.91 85.6 180 top
R159  6.8K  [R0402]  130.94 93.34 90 top
R160  6.8K  [R0402]  118.11 68.58 0 top
R161  10K  [R0402]  124.97 19.18 90 bottom
R162  10K  [R0402]  124.97 19.18 90 top
R163  10K  [R0402]  123.83 19.18 90 bottom
R164  10K  [R0402]  123.83 19.18 90 top
R165  1K  [R0402]  126.87 60.83 90 bottom
R166  3.4K  [R0402]  129.92 60.83 90 bottom
R167  1K  [R0402]  126.87 38.99 90 bottom
R168  3.4K  [R0402]  131.44 39.11 90 top
R169  15K  [R0402]  115.44 36.07 270 bottom
R170  0R  [R0402]  113.16 33.53 270 bottom
R171  0R  [R0402]  116.71 36.07 270 bottom
R172  100K  [R0402]  83.69 79.63 90 top
R173  0R  [R0402]  114.17 36.07 270 bottom
R174  30K  [R0402]  82.68 79.63 270 top
R175  1K  [R0402]  81.79 82.68 0 bottom
R176  10K  [R0402]  81.79 81.66 180 bottom
R177  4.7K  [R0402]  119.38 78.36 0 bottom
R178  22R  [R0402]  119.38 79.37 0 bottom
R179  22R  [R0402]  117.22 79.37 0 bottom
R180  100R  [R0402]  104.9 67.56 180 top
R181  100R  [R0402]  104.9 68.58 180 top
R182  2.2R  [R0402]  100.71 67.56 180 top
R183  2.2R  [R0402]  100.71 68.58 180 top
R184  0R  [R0402]  58.17 56.89 180 bottom
R185  10K  [R0402]  54.74 67.05 180 bottom
R186  4.7R  [R0402]  42.29 68.2 270 bottom
R187  0R  [R0402]  42.29 66.17 90 bottom
R188  10K  [R0402]  54.74 68.2 180 bottom
R189  0R  [R0402]  39.75 61.21 90 bottom
R190  22R  [R0402]  54.74 65.78 180 bottom
R191  22R  [R0402]  53.21 63.37 90 bottom
R192  100R  [R0402]  54.86 83.44 90 top
R193  22R  [R0402]  52.2 63.37 90 bottom
R194  22R  [R0402]  51.18 63.37 90 bottom
R195  22R  [R0402]  50.16 63.37 90 bottom
R196  1.1K  [R0402]  56.9 83.44 90 top
R197  22R  [R0402]  50.42 73.28 270 bottom
R198  22R  [R0402]  49.4 73.28 270 bottom
R199  0R  [R0402]  57.91 83.44 270 top
R200  10K  [R0402]  48.39 73.28 270 bottom
R201  0R  [R0402]  58.93 83.44 270 top
R202  1.1K  [R0402]  59.94 83.44 270 top
R203  20K  [R0402]  31.62 74.93 90 bottom
R204  20K  [R0402]  30.61 74.93 90 bottom
R205  10K  [R0402]  44.45 83.44 90 top
R206  1K  [R0402]  46.1 94.61 270 bottom
R207  120R  [R0402]  52.45 75.69 90 bottom
R208  2.2K  [R0402]  50.93 77.21 180 bottom
R209  20K  [R0402]  31.11 77.47 0 bottom
R210  0R  [R0603]  41.66 80.01 180 bottom
R211  NC  [R0402]  41.66 81.28 180 bottom
R212  100K  [R0402]  31.11 78.48 180 bottom
R213  0R  [R0603]  37.85 80.01 0 bottom
R214  4.7K  [R0402]  35.43 83.44 270 bottom
R215  NC  [R0402]  37.85 81.28 0 bottom
R216  300K  [R0402]  45.72 83.44 90 bottom
R217  0R  [R0402]  45.97 101.09 0 bottom
R218  2.2K  [R0402]  48.64 77.21 180 bottom
R219  0R  [R0402]  45.97 99.82 180 bottom
R220  2.2R  [R0402]  34.54 91.31 270 top
R221  2.2R  [R0402]  33.53 91.31 270 top
R222  0R  [R0402]  31.24 91.31 270 top
R223  0R  [R0402]  32.26 91.31 270 top
R224  0R  [R0402]  26.16 91.31 270 top
R225  0R  [R0402]  27.18 91.31 270 top
R226  100K  [R0402]  30.99 91.57 270 bottom
R227  100K  [R0402]  34.04 91.57 270 bottom
R228  2M  [R0402]  33.53 93.09 0 bottom
R229  2M  [R0402]  31.5 93.09 180 bottom
R230  10K  [R0402]  23.11 65.66 90 bottom
R231  10K  [R0402]  21.97 65.66 90 bottom
R232  10K  [R0402]  24.26 65.66 90 bottom
R233  4.7K  [R0402]  44.83 80.01 180 bottom
R234  NC  [R0402]  43.31 73.28 90 bottom
R235  3.4K  [R0402]  28.07 90.04 0 bottom
R236  1K  [R0402]  19.94 89.03 0 bottom
R237  10K  [R0402]  19.94 90.04 180 bottom
R238  0R  [R0402]  26.04 22.48 0 bottom
R239  100R  [R0402]  6.22 40.27 90 bottom
R240  0R  [R0402]  117.22 74.44 0 bottom
SS1  M2.5X1.5mm  [SMTSO-M2R5]  13.3 73.05 0 top
SS2  M2.5X1.5mm  [SMTSO-M2R5]  13.3 27.05 0 top
SS3  M2.5X1.5mm  [SMTSO-M2R5]  79.3 27.05 0 top
SS4  M2.5X1.5mm  [SMTSO-M2R5]  79.3 73.05 0 top
SS5  M2.5X3mm  [SMTSO-M2R5]  119.9 26.95 0 top
SS6  M2.5X3mm  [SMTSO-M2R5]  95.7 26.95 0 top
SW1  SW_PB_ESW  [SW4-4R20X3R25-SM]  4.57 19 180 top
SW2  SW_PB_ESW  [SW4-4R20X3R25-SM]  4.57 23.39 180 top
SW3  SW_PB_ESW  [SW4-4R20X3R25-SM]  4.57 27.77 180 top
SW4  SW_PB_ESW  [SW4-4R20X3R25-SM]  4.57 32.16 180 top
SW5  SW_PB_ESW  [SW4-4R20X3R25-SM]  4.57 36.55 180 top
SW6  SW_PB_ESW  [SW4-4R20X3R25-SM]  4.57 40.93 0 top
U1  LPW5209AB5F  [SOT23-5]  25.02 43.05 270 bottom
U2  LPW5209AB5F  [SOT23-5]  25.02 47.88 270 bottom
U3  ASP9135ZC-R  [SOT23_6]  4.83 52.96 90 top
U4  MP8759GD-Z  [QFN12-2R00X3R00]  4.7 70.86 270 top
U5  74LVC1G125GW  [SOT-353]  22.23 17.02 270 bottom
U6  74LVC1G125GW  [SOT-353]  27.81 17.02 270 bottom
U7  IRM-V838M3-C/TR1  [SMD4-6R80X2R50]  12 11 180 top
U8  BM8563EMA  [MSOP-8]  4.45 85.09 90 bottom
U9  SIT3232EESE  [SOIC16]  41.15 46.1 90 bottom
U10  SIT3088EESA  [SOP8]  90.3 46.1 0 bottom
U11  SIT3088EESA  [SOP8]  82.42 46.1 0 bottom
U12  SIT1042AQT/3  [SOP8]  73.03 46.1 0 bottom
U13  SIT1042AQT/3  [SOP8]  64.9 46.1 0 bottom
U14  RTL8211F  [QFP_40P_R]  111.63 68.32 270 bottom
U15  TL8821CUB  [RL-UM02WBS-8723BU]  107.82 44.93 180 top
U16  D2550-3R3  [SON10_2R50X1R00X0R50]  88.9 85.09 0 bottom
U17  D2550-3R3  [SON10_2R50X1R00X0R50]  84.45 85.09 0 bottom
U18  D2550-3R3  [SON10_2R50X1R00X0R50]  96.9 64.39 90 bottom
U19  CH334F  [QFN24]  89.28 68.32 180 bottom
U20  LPW5209AB5F  [SOT23-5]  86.87 99.06 180 bottom
U21  LPW5209AB5F  [SOT23-5]  100.2 99.06 180 bottom
U22  D2550-3R3  [SON10_2R50X1R00X0R50]  64.26 89.53 180 top
U23  D2550-3R3  [SON10_2R50X1R00X0R50]  68.71 89.53 180 top
U24  LPW5209AB5F  [SOT23-5]  118.11 60.2 180 top
U25  LPW5209AB5F  [SOT23-5]  128.78 88.39 0 top
U26  LPW5209AB5F  [SOT23-5]  128.78 93.34 0 top
U27  LPW5209AB5F  [SOT23-5]  118.11 66.04 180 top
U28  LPW5209AB5F  [SOT23-5]  129.29 61.21 0 top
U29  LPW5209AB5F  [SOT23-5]  129.29 39.11 0 top
U30  ASP9135ZC-R  [SOT23_6]  83.19 83.44 180 top
U32  NUP5120X6T1G  [SOT563]  115.44 31.37 90 bottom
U33  ES8388  [QFN28_0R45-4X4EP2R6X2R6]  48.77 68.32 180 bottom
U34  8002A  [SOP8]  31.11 81.66 270 bottom
U35  D2550-3R3  [SON10_2R50X1R00X0R50]  30.35 93.72 0 top
U36  D2550-3R3  [SON10_2R50X1R00X0R50]  25.65 93.72 0 top
U37  D2550-3R3  [SON10_2R50X1R00X0R50]  36.45 96.65 0 bottom
U38  LPW5209AB5F  [SOT23-5]  24.77 91.95 270 bottom
U39  FUSB302BMPX  [WQFN14-0R50-2R5X2R5EP1R45X1R45]  23.24 69.47 180 bottom
Y1  32.768KHz  [3215]  4.45 89.28 180 bottom
Y2  25MHz  [3225]  104.52 68.32 270 bottom
Y3  12MHz  [3225]  95.76 68.32 270 bottom
Z1  KLXES15AAA1  [ES0402]  4.19 19.56 90 bottom
Z2  KLXES15AAA1  [ES0402]  4.19 24.02 90 bottom
Z3  KLXES15AAA1  [ES0402]  23.24 14.98 0 bottom
Z4  KLXES15AAA1  [ES0402]  26.8 14.98 180 bottom
Z5  KLXES15AAA1  [ES0402]  4.19 28.32 90 bottom
Z6  KLXES15AAA1  [ES0402]  4.19 32.76 90 bottom
Z7  KLXES15AAA1  [ES0402]  4.19 37.1 90 bottom
Z8  KLXES15AAA1  [ES0402]  50.93 79.75 180 bottom
Z9  KLXES15AAA1  [ES0402]  45.09 94.61 270 bottom
Z10  KLXES15AAA1  [ES0402]  44.7 88.01 90 bottom
Z11  KLXES15AAA1  [ES0402]  48.64 79.75 0 bottom
Z12  KLXES15AAA1  [ES0402]  4.19 40.27 270 bottom

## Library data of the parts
C1 C19 C151 = CAP
C2-C18 C21-C96 C99-C111 C123-C145 C148-C150 C152-C164 C167-C184 C186-C196 C203-C207 C209-C212 = CAP_NP
C20 C113-C120 C185 = CAP_NP: signal model: CAP_NP_C0402_DISCRETE_0.22UF_0.22uF
C97 C98 C112 C146 C147 C165 C166 C197-C202 = CAP_NP: signal model: CAP_NP_C0402_DISCRETE_0.1UF_0.1uF
C121 C122 = CAP_NP: signal model: CAP_NP_C0402_DISCRETE_1UF_1uF
CN1 = WIFI_ANT
D1 D6-D18 D20-D22 D24-D27 D29-D36 Z1-Z12 = DIODE BI-DIR TRIG
D2 = DIODE
D3 D4 LED1 = LED
D5 = BAT54C
D19 D23 D28 = DIODE_SCHTKY
F1 = FUSE
H1-H4 SS1-SS6 = SPACER
J1 = DC-044A-20A
J2 J8 J11 J13 J28 J29 = 1X2PIN
J3 J5 = DF40C-100DP
J4 J6 = SGDBM-05-100P-H10
J7 = 1X4PIN
J9 = CON6
J10 = TF_Card
J12 J14 = CON4
J15 = HY911130A
J16 = USB3D0_USB2D0-A-D
J17 = USB_AF
J18 = A111926-A-05-R
J19 J20 = FPC-30P
J21-J24 = FPC-24P
J25 = MINI-PCIE
J26 J27 = MIC_JACK
J30 = TYPE-C-24P
J31 = SIM-7-1
L1-L3 L6 = IND
L5 L7 = BEAD
P1 = MIC_POM
Q1 Q6 = MOSFET_P
Q2-Q5 = NPN
Q7-Q15 = 2SK3018
Q16 Q17 = MOSFET N
R1-R45 R48 R49 R51 R52 R56 R67-R83 R86 R93-R95 R98 R100-R107 R110 R111 R118 R121-R181 R184-R189 R192 R196 R199-R219 R226-R240 = RES
R46 R47 R53-R55 R57-R65 R84 R85 R87-R90 R96 R97 R99 R190 R191 R193-R195 R197 R198 = RES: signal model: RES_R0402_DISCRETE_22R_22R
R50 R66 R91 R92 R222-R225 = RES: signal model: RES_R0402_DISCRETE_0R_0R
R108 R109 R112-R117 R119 R120 R182 R183 R220 R221 = RES: signal model: RES_R0402_DISCRETE_2.2R_2.2R
SW1-SW6 = SW_PB_ESW
U1 U2 U20 U21 U24-U29 U38 = LPW5209AB5F
U3 U30 = TP6327GS6
U4 = MP8759GD-Z
U5 U6 = 74LVC1G125
U7 = IRM-V838M3-C/TR1
U8 = HYM8563S
U9 = MAX3232CSE
U10 U11 = SIT3088E-8P
U12 U13 = TJA1057GT3_8P
U14 = RTL8211F
U15 = RTL8723
U16-U18 U22 U23 U35-U37 = RCLAMP0524P
U19 = CH334F
U32 = NUP5120-D
U33 = ES8388
U34 = 8002A
U39 = FUSB302BMPX
Y1 = CRYSTAL_2P
Y2 Y3 = CRYSTAL_4P

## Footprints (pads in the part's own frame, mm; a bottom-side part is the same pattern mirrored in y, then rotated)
3215
  rect 1.4x1.2 smd: 1(-1.001,0) 2(1.001,0)
3225
  rect 1.3x1 smd: 1(-1.15,-0.75) 2(1.15,-0.75) 3(1.15,0.75) 4(-1.15,0.75)
C0201
  rect 0.35x0.35 smd: 1(-0.275,0) 2(0.275,0)
C0402
  rect 0.599x0.599 smd: 1(-0.5,0) 2(0.5,0)
C0603
  rect 0.8x0.8 smd: 1(-0.8,0) 2(0.8,0)
C0805
  rect 1.16x1.47 smd: 1(-0.89,0) 2(0.89,0)
CASE-B_3528
  rect 1.2x2.4 smd: 1(-1.45,0) 2(1.45,0)
CON_RA_HDMI_19P_0P5_SM
  rect 0.305x2.692 smd: 1(4.5,5.375) 2(4,5.375) 3(3.5,5.375) 4(3,5.375) 5(2.5,5.375) 6(2,5.375) 7(1.5,5.375) 8(1,5.375) 9(0.5,5.375) 10(0,5.375) 11(-0.5,5.375) 12(-1,5.375) 13(-1.5,5.375) 14(-2,5.375) 15(-2.5,5.375) 16(-3,5.375) 17(-3.5,5.375) 18(-4,5.375) 19(-4.5,5.375)
  oval 1.499x2.692 hole 0.889x2.108: G1(7.25,4.525) G2(-7.25,4.525)
  oval 1.499x2.286 hole 0.889x1.676: G3(7.25,-1.475) G4(-7.25,-1.475)
DB2ERC-3P81-4P
  rect 1.8x1.8 hole 1.2: 1(-5.715,0)
  round 1.8 hole 1.2: 2(-1.905,0) 3(1.905,0) 4(5.715,0)
DB2ERC-3P81-6P
  rect 1.8x1.8 hole 1.2: 1(-9.525,0)
  round 1.8 hole 1.2: 2(-5.715,0) 3(-1.905,0) 4(1.905,0) 5(5.715,0) 6(9.525,0)
DC_IN_TH_3P_10R1X11R6
  round 1.999 hole 1.999 unplated: (-1.699,-1.25)
  oval 2.4x1.001 hole 1.801x0.399: 1(-2.751,-4.9) 5(-2.751,4.9)
  oval 2.7x1.5 hole 1.7x0.5: 2(4.501,-1.25) 3(4.501,4.049) 4(4.501,-4.45)
DF40C-100DP-0P4V
  rect 0.2x1.2 smd: 1(-9.8,1.325) 2(-9.8,-1.325) 3(-9.4,1.325) 4(-9.4,-1.325) 5(-9,1.325) 6(-9,-1.325) 7(-8.6,1.325) 8(-8.6,-1.325) 9(-8.2,1.325) 10(-8.2,-1.325) 11(-7.8,1.325) 12(-7.8,-1.325) 13(-7.4,1.325) 14(-7.4,-1.325) 15(-7,1.325) 16(-7,-1.325) 17(-6.6,1.325) 18(-6.6,-1.325) 19(-6.2,1.325) 20(-6.2,-1.325) 21(-5.8,1.325) 22(-5.8,-1.325) 23(-5.4,1.325) 24(-5.4,-1.325) 25(-5,1.325) 26(-5,-1.325) 27(-4.6,1.325) 28(-4.6,-1.325) 29(-4.2,1.325) 30(-4.2,-1.325) 31(-3.8,1.325) 32(-3.8,-1.325) 33(-3.4,1.325) 34(-3.4,-1.325) 35(-3,1.325) 36(-3,-1.325) 37(-2.6,1.325) 38(-2.6,-1.325) 39(-2.2,1.325) 40(-2.2,-1.325) 41(-1.8,1.325) 42(-1.8,-1.325) 43(-1.4,1.325) 44(-1.4,-1.325) 45(-1,1.325) 46(-1,-1.325) 47(-0.6,1.325) 48(-0.6,-1.325) 49(-0.2,1.325) 50(-0.2,-1.325) 51(0.2,1.325) 52(0.2,-1.325) 53(0.6,1.325) 54(0.6,-1.325) 55(1,1.325) 56(1,-1.325) 57(1.4,1.325) 58(1.4,-1.325) 59(1.8,1.325) 60(1.8,-1.325) 61(2.2,1.325) 62(2.2,-1.325) 63(2.6,1.325) 64(2.6,-1.325) 65(3,1.325) 66(3,-1.325) 67(3.4,1.325) 68(3.4,-1.325) 69(3.8,1.325) 70(3.8,-1.325) 71(4.2,1.325) 72(4.2,-1.325) 73(4.6,1.325) 74(4.6,-1.325) 75(5,1.325) 76(5,-1.325) 77(5.4,1.325) 78(5.4,-1.325) 79(5.8,1.325) 80(5.8,-1.325) 81(6.2,1.325) 82(6.2,-1.325) 83(6.6,1.325) 84(6.6,-1.325) 85(7,1.325) 86(7,-1.325) 87(7.4,1.325) 88(7.4,-1.325) 89(7.8,1.325) 90(7.8,-1.325) 91(8.2,1.325) 92(8.2,-1.325) 93(8.6,1.325) 94(8.6,-1.325) 95(9,1.325) 96(9,-1.325) 97(9.4,1.325) 98(9.4,-1.325) 99(9.8,1.325) 100(9.8,-1.325)
  rect 0.35x1.2 smd: 101(-10.275,1.325) 102(-10.275,-1.325) 103(10.275,1.325) 104(10.275,-1.325)
DF40HC-100DS-0P4V
  rect 0.2x0.8 smd: 1(-9.8,-1.7) 2(-9.8,1.7) 3(-9.4,-1.7) 4(-9.4,1.7) 5(-9,-1.7) 6(-9,1.7) 7(-8.6,-1.7) 8(-8.6,1.7) 9(-8.2,-1.7) 10(-8.2,1.7) 11(-7.8,-1.7) 12(-7.8,1.7) 13(-7.4,-1.7) 14(-7.4,1.7) 15(-7,-1.7) 16(-7,1.7) 17(-6.6,-1.7) 18(-6.6,1.7) 19(-6.2,-1.7) 20(-6.2,1.7) 21(-5.8,-1.7) 22(-5.8,1.7) 23(-5.4,-1.7) 24(-5.4,1.7) 25(-5,-1.7) 26(-5,1.7) 27(-4.6,-1.7) 28(-4.6,1.7) 29(-4.2,-1.7) 30(-4.2,1.7) 31(-3.8,-1.7) 32(-3.8,1.7) 33(-3.4,-1.7) 34(-3.4,1.7) 35(-3,-1.7) 36(-3,1.7) 37(-2.6,-1.7) 38(-2.6,1.7) 39(-2.2,-1.7) 40(-2.2,1.7) 41(-1.8,-1.7) 42(-1.8,1.7) 43(-1.4,-1.7) 44(-1.4,1.7) 45(-1,-1.7) 46(-1,1.7) 47(-0.6,-1.7) 48(-0.6,1.7) 49(-0.2,-1.7) 50(-0.2,1.7) 51(0.2,-1.7) 52(0.2,1.7) 53(0.6,-1.7) 54(0.6,1.7) 55(1,-1.7) 56(1,1.7) 57(1.4,-1.7) 58(1.4,1.7) 59(1.8,-1.7) 60(1.8,1.7) 61(2.2,-1.7) 62(2.2,1.7) 63(2.6,-1.7) 64(2.6,1.7) 65(3,-1.7) 66(3,1.7) 67(3.4,-1.7) 68(3.4,1.7) 69(3.8,-1.7) 70(3.8,1.7) 71(4.2,-1.7) 72(4.2,1.7) 73(4.6,-1.7) 74(4.6,1.7) 75(5,-1.7) 76(5,1.7) 77(5.4,-1.7) 78(5.4,1.7) 79(5.8,-1.7) 80(5.8,1.7) 81(6.2,-1.7) 82(6.2,1.7) 83(6.6,-1.7) 84(6.6,1.7) 85(7,-1.7) 86(7,1.7) 87(7.4,-1.7) 88(7.4,1.7) 89(7.8,-1.7) 90(7.8,1.7) 91(8.2,-1.7) 92(8.2,1.7) 93(8.6,-1.7) 94(8.6,1.7) 95(9,-1.7) 96(9,1.7) 97(9.4,-1.7) 98(9.4,1.7) 99(9.8,-1.7) 100(9.8,1.7)
EAR_JACK
  oval 1.4x2.6 hole 1x2: 1(-6.1,-0.9) 2(-3.7,1.1) 3(1.8,1.1) 4(5.9,-0.9) 5(0,-0.9)
EC6P3
  rect 1.001x1.999 smd: 1(0,2.8) 2(0,-2.8)
ES0402
  rect 0.599x0.599 smd: 1(-0.5,0) 2(0.5,0)
F1812
  rect 1.78x3.3 smd: 1(-2.305,0) 2(2.305,0)
FPC-30P-0P5
  rect 0.3x1.3 smd: 1(-7.25,1.35) 2(-6.75,1.35) 3(-6.25,1.35) 4(-5.75,1.35) 5(-5.25,1.35) 6(-4.75,1.35) 7(-4.25,1.35) 8(-3.75,1.35) 9(-3.25,1.35) 10(-2.75,1.35) 11(-2.25,1.35) 12(-1.75,1.35) 13(-1.25,1.35) 14(-0.75,1.35) 15(-0.25,1.35) 16(0.25,1.35) 17(0.75,1.35) 18(1.25,1.35) 19(1.75,1.35) 20(2.25,1.35) 21(2.75,1.35) 22(3.25,1.35) 23(3.75,1.35) 24(4.25,1.35) 25(4.75,1.35) 26(5.25,1.35) 27(5.75,1.35) 28(6.25,1.35) 29(6.75,1.35) 30(7.25,1.35)
  rect 1.6x2 smd: 31(9.4,-1.35) 32(-9.4,-1.35)
FPC_24P_0P5
  rect 0.3x1.3 smd: 1(-5.75,-1.351) 2(-5.25,-1.351) 3(-4.75,-1.351) 4(-4.25,-1.351) 5(-3.75,-1.351) 6(-3.25,-1.351) 7(-2.75,-1.351) 8(-2.25,-1.351) 9(-1.75,-1.351) 10(-1.25,-1.351) 11(-0.75,-1.351) 12(-0.25,-1.351) 13(0.25,-1.351) 14(0.75,-1.351) 15(1.25,-1.351) 16(1.75,-1.351) 17(2.25,-1.351) 18(2.75,-1.351) 19(3.25,-1.351) 20(3.75,-1.351) 21(4.25,-1.351) 22(4.75,-1.351) 23(5.25,-1.351) 24(5.75,-1.351)
  rect 1.6x2 smd: 25(7.45,1.351) 26(-7.45,1.351)
GH1P25_TH_2P
  rect 0.9x0.9 hole 0.5: 1(-0.625,0)
  round 0.9 hole 0.5: 2(0.625,0)
HDR1X2-2R54-TM-VM
  rect 1.6x1.6 hole 1: 1(-1.27,0)
  round 1.6 hole 1: 2(1.27,0)
HY911130A
  round 3.25 hole 3.25 unplated: (-5.715,0) (5.715,0)
  round 1.6 hole 1: 1(5.72,-8.89) 2(4.45,-6.35) 3(3.18,-8.89) 4(1.91,-6.35) 5(0.64,-8.89) 6(-0.63,-6.35) 7(-1.9,-8.89) 8(-3.17,-6.35) 9(-4.44,-8.89) 10(-5.71,-6.35)
  round 1.8 hole 1.2: 11(6.625,4.9) 12(4.085,4.9) 13(-4.085,4.9) 14(-6.625,4.9)
  round 2.43 hole 1.83: 15(7.745,-3.05) 16(-7.745,-3.05)
L0518
  rect 1.9x2.5 smd: 1(-2.05,0) 2(2.05,0)
L0603
  rect 0.8x0.8 smd: 1(-0.8,0) 2(0.8,0)
L2520
  rect 1.118x2.032 smd: 1(-0.959,0) 2(0.959,0)
L4520
  rect 1.4x2.3 smd: 1(-1.8,0) 2(1.8,0)
LED0603
  rect 0.93x0.98 smd: 1(0.77,0) 2(-0.77,0)
MIC2-4R00-TM
  round 1.1 hole 0.7: 1(-0.7,0) 2(0.7,0)
MSOP-8
  rect 0.3x1 smd: 1(-0.975,-2.2) 2(-0.325,-2.2) 3(0.325,-2.2) 4(0.975,-2.2) 5(0.975,2.2) 6(0.325,2.2) 7(-0.325,2.2) 8(-0.975,2.2)
NANO_SIM
  round 0.9 hole 0.9 unplated: (-5,-5.49) (3.5,-5.49)
  rect 0.5x1.3 smd: 1(0.25,6.74) 2(-2.29,6.74) 3(-4.83,6.74) 4(2.47,6.74) 5(1.52,6.74) 6(-1.02,6.74) 7(-3.56,6.74)
  rect 1x2.1 smd: 8(-6.5,5.26) 9(6.5,5.26) 10(-6.5,-6.74) 11(6.5,-6.74)
NPTH_M3
  round 3.2 hole 3.2 unplated: (0,0)
PCIE_52P
  round 1.6 hole 1.6 unplated: (-12.5,0)
  round 1.1 hole 1.1 unplated: (12.5,0)
  rect 0.6x2 smd: 1(-11.8,-4.1) 2(-11.4,4.1) 3(-11,-4.1) 4(-10.6,4.1) 5(-10.2,-4.1) 6(-9.8,4.1) 7(-9.4,-4.1) 8(-9,4.1) 9(-8.6,-4.1) 10(-8.2,4.1) 11(-7.8,-4.1) 12(-7.4,4.1) 13(-7,-4.1) 14(-6.6,4.1) 15(-6.2,-4.1) 16(-5.8,4.1) 17(-2.2,-4.1) 18(-1.8,4.1) 19(-1.4,-4.1) 20(-1,4.1) 21(-0.6,-4.1) 22(-0.2,4.1) 23(0.2,-4.1) 24(0.6,4.1) 25(1,-4.1) 26(1.4,4.1) 27(1.8,-4.1) 28(2.2,4.1) 29(2.6,-4.1) 30(3,4.1) 31(3.4,-4.1) 32(3.8,4.1) 33(4.2,-4.1) 34(4.6,4.1) 35(5,-4.1) 36(5.4,4.1) 37(5.8,-4.1) 38(6.2,4.1) 39(6.6,-4.1) 40(7,4.1) 41(7.4,-4.1) 42(7.8,4.1) 43(8.2,-4.1) 44(8.6,4.1) 45(9,-4.1) 46(9.4,4.1) 47(9.8,-4.1) 48(10.2,4.1) 49(10.6,-4.1) 50(11,4.1) 51(11.4,-4.1) 52(11.8,4.1)
  rect 2.15x2.6 smd: 53(14.65,-3.5) 54(-14.65,-3.5)
PH-1X2-2P0_L
  rect 1.1x1.1 hole 0.7: 1(-1,0)
  round 1.1 hole 0.7: 2(1,0)
QFN12-2R00X3R00
  oval 1.4x0.25 smd: 1(-0.6,0.5) 2(-0.6,-0.5) 7(0.6,0)
  oval 0.25x0.8 smd: 3(-0.75,-1.45) 4(-0.25,-1.45) 5(0.25,-1.45) 6(0.75,-1.45) 9(0.75,1.45) 10(0.25,1.45) 11(-0.25,1.45) 12(-0.75,1.45)
  oval 0.8x0.25 smd: 8(0.9,0.5)
QFN24
  rect 1x0.3 smd: 1(-2.1,1.25) 2(-2.1,0.75) 3(-2.1,0.25) 4(-2.1,-0.25) 5(-2.1,-0.75) 6(-2.1,-1.25) 13(2.1,-1.25) 14(2.1,-0.75) 15(2.1,-0.25) 16(2.1,0.25) 17(2.1,0.75) 18(2.1,1.25)
  rect 0.3x1 smd: 7(-1.25,-2.1) 8(-0.75,-2.1) 9(-0.25,-2.1) 10(0.25,-2.1) 11(0.75,-2.1) 12(1.25,-2.1) 19(1.25,2.1) 20(0.75,2.1) 21(0.25,2.1) 22(-0.25,2.1) 23(-0.75,2.1) 24(-1.25,2.1)
  rect 2x2 smd: 25(0,0)
QFN28_0R45-4X4EP2R6X2R6
  oval 0.8x0.2 smd: 1(-2,1.35)
  rect 0.8x0.2 smd: 2(-2,0.9) 3(-2,0.45) 4(-2,0) 5(-2,-0.45) 6(-2,-0.9) 7(-2,-1.35) 15(2,-1.35) 16(2,-0.9) 17(2,-0.45) 18(2,0) 19(2,0.45) 20(2,0.9) 21(2,1.35)
  rect 0.2x0.8 smd: 8(-1.35,-2) 9(-0.9,-2) 10(-0.45,-2) 11(0,-2) 12(0.45,-2) 13(0.9,-2) 14(1.35,-2) 22(1.35,2) 23(0.9,2) 24(0.45,2) 25(0,2) 26(-0.45,2) 27(-0.9,2) 28(-1.35,2)
  rect 2x2 smd: 29(0,0)
QFP_40P_R
  oval 0.8x0.22 smd: 1(-2.5,1.8) 2(-2.5,1.4) 3(-2.5,1) 4(-2.5,0.6) 5(-2.5,0.2) 6(-2.5,-0.2) 7(-2.5,-0.6) 8(-2.5,-1) 9(-2.5,-1.4) 10(-2.5,-1.8) 21(2.5,-1.8) 22(2.5,-1.4) 23(2.5,-1) 24(2.5,-0.6) 25(2.5,-0.2) 26(2.5,0.2) 27(2.5,0.6) 28(2.5,1) 29(2.5,1.4) 30(2.5,1.8)
  oval 0.22x0.8 smd: 11(-1.8,-2.5) 12(-1.4,-2.5) 13(-1,-2.5) 14(-0.6,-2.5) 15(-0.2,-2.5) 16(0.2,-2.5) 17(0.6,-2.5) 18(1,-2.5) 19(1.4,-2.5) 20(1.8,-2.5) 31(1.8,2.5) 32(1.4,2.5) 33(1,2.5) 34(0.6,2.5) 35(0.2,2.5) 36(-0.2,2.5) 37(-0.6,2.5) 38(-1,2.5) 39(-1.4,2.5) 40(-1.8,2.5)
  rect 3x3 smd: 41(0,0)
R0402
  rect 0.599x0.599 smd: 1(-0.5,0) 2(0.5,0)
R0603
  rect 0.8x0.8 smd: 1(-0.8,0) 2(0.8,0)
R0805
  rect 1.016x1.143 smd: 1(-1.016,0) 2(1.016,0)
RL-UM02WBS-8723BU
  oval 2x1 smd: 1(-6.3,3.97) 2(-6.3,1.97) 3(-6.3,-1.01) 4(-6.3,-3.17) 5(6.3,3.5) 6(6.3,0.97) 7(6.3,-2.53) 8(6.3,-5.33)
  oval 1x2 smd: 9(3.65,-6.9) 10(2.38,-6.9) 11(1.11,-6.9) 12(-0.16,-6.9) 13(-1.43,-6.9) 14(-2.7,-6.9)
SMA_CA
  rect 2.1x1.8 smd: 1(-2.2,0) 2(2.2,0)
SMB-CA
  rect 2.4x2.8 smd: 1(-2.3,0) 2(2.3,0)
SMD4-6R80X2R50
  rect 0.8x1.2 smd: 1(1.905,0) 2(0.635,0) 3(-0.635,0) 4(-1.905,0)
SMTSO-M2R5
  round 6.2 hole 4.22: 1(0,0)
SOD523
  rect 0.6x0.7 smd: 1(-0.71,0) 2(0.71,0)
SOD-123
  rect 1.2x1.4 smd: 1(1.7,0) 2(-1.7,0)
SOIC16
  oval 2.032x0.61 smd: 1(-2.789,4.44) 2(-2.789,3.18) 3(-2.789,1.9) 4(-2.789,0.64) 5(-2.789,-0.64) 6(-2.789,-1.9) 7(-2.789,-3.18) 8(-2.789,-4.44) 9(2.789,-4.44) 10(2.789,-3.18) 11(2.789,-1.9) 12(2.789,-0.64) 13(2.789,0.64) 14(2.789,1.9) 15(2.789,3.18) 16(2.789,4.44)
SON10_2R50X1R00X0R50
  rect 0.2x0.68 smd: 1(-1,-0.437) 2(-0.5,-0.437) 4(0.5,-0.437) 5(1,-0.437) 6(1,0.437) 7(0.5,0.437) 9(-0.5,0.437) 10(-1,0.437)
  rect 0.4x0.68 smd: 3(0,-0.437) 8(0,0.437)
SOP8
  oval 0.6x1.8 smd: 1(-1.905,-2.5) 2(-0.635,-2.5) 3(0.635,-2.5) 4(1.905,-2.5) 5(1.905,2.5) 6(0.635,2.5) 7(-0.635,2.5) 8(-1.905,2.5)
SOT23
  rect 0.914x0.914 smd: 1(-0.953,-0.991) 2(0.953,-0.991)
  rect 0.914x1.27 smd: 3(0,1.041)
SOT23-5
  rect 0.599x1.199 smd: 1(-0.95,-1.25) 2(0,-1.25) 3(0.95,-1.25) 4(0.95,1.25) 5(-0.95,1.25)
SOT23_6
  rect 0.7x0.9 smd: 1(-0.95,-1.2) 2(0,-1.2) 3(0.95,-1.2) 4(0.95,1.2) 5(0,1.2) 6(-0.95,1.2)
SOT563
  rect 0.3x0.45 smd: 1(-0.5,-0.675) 2(0,-0.675) 3(0.5,-0.675) 4(0.5,0.675) 5(0,0.675) 6(-0.5,0.675)
SOT-353
  rect 0.406x1.194 smd: 1(-0.65,-0.9) 2(0,-0.9) 3(0.65,-0.9) 4(0.65,0.9) 5(-0.65,0.9)
SW4-4R20X3R25-SM
  rect 1.2x0.65 smd: 1(-2.15,1.075) 2(2.15,1.075) 3(2.15,-1.075) 4(-2.15,-1.075)
TFCARD
  round 1 hole 1 unplated: (-4,0) (4,0)
  rect 0.7x1.6 smd: 1(3.2,10.5) 2(2.1,10.5) 3(1,10.5) 4(-0.1,10.5) 5(-1.2,10.5) 6(-2.3,10.5) 7(-3.4,10.5) 8(-4.5,10.5) 9(-5.6,10.5)
  rect 1.2x1.778 smd: 10(-6.8,10)
  rect 1.524x2.413 smd: 11(-6.8,0.4) 12(8.7,0.4)
  rect 1.778x1.778 smd: 13(7.8,10)
UFL-3
  rect 1.05x1.05 smd: 1(0,-1.5)
  rect 1.05x2.2 smd: 2(-1.5,0) 3(1.5,0)
unnamed#2
  round 1.016 smd: (0,0)
USB3D0-AF-18P
  round 1.1 hole 0.7: 1(-3.5,-1.501) 2(-1.001,-1.501) 3(1.001,-1.501) 4(3.5,-1.501) 5(4,0) 6(1.999,0) 7(0,0) 8(-1.999,0) 9(-4,0) 10(-3.5,1.699) 11(-1.001,1.699) 12(1.001,1.699) 13(3.5,1.699) 14(4,3.2) 15(1.999,3.2) 16(0,3.2) 17(-1.999,3.2) 18(-4,3.2)
  round 3.2 hole 2.4: 19(6.571,-3.5) 20(6.571,2.179) 21(-6.571,2.179) 22(-6.571,-3.5)
USB-AF
  round 1 hole 0.6: 1(0,3.002) 2(0,1) 3(0,-1.002) 4(0,-3.004)
  round 2.2 hole 1.6: 5(2.749,-3.5) 6(2.749,3.5) 7(-2.751,3.5) 8(-2.751,-3.5)
USB-C-SMD_TYC-324G
  oval 1.5x1 hole 1.2x0.5: (-4.06,1.45) (4.06,1.45)
  round 0.5 hole 0.5 unplated: (-3.4,0.57) (3.4,0.57)
  oval 1x2.2 hole 0.6x1.6: 1(-4.32,1.93) 4(4.32,1.93)
  oval 1.2x2.4 hole 0.6x1.9: 2(-4.32,-2.62) 3(4.32,-2.62)
  rect 0.3x1 smd: A1(-2.62,2.62) A2(-2.13,2.62) A3(-1.63,2.62) A4(-1.13,2.62) A5(-0.62,2.62) A6(-0.12,2.62) A7(0.38,2.62) A8(0.88,2.62) A9(1.37,2.62) A10(1.87,2.62) A11(2.37,2.62) A12(2.88,2.62) B1(2.63,1.28) B2(2.13,1.28) B3(1.63,1.28) B4(1.13,1.28) B5(0.62,1.28) B6(0.12,1.28) B7(-0.38,1.28) B8(-0.87,1.28) B9(-1.37,1.28) B10(-1.87,1.28) B11(-2.37,1.28) B12(-2.88,1.28)
WQFN14-0R50-2R5X2R5EP1R45X1R45
  rect 0.6x0.3 smd: 1(-1.21,0.5) 2(-1.21,0) 3(-1.21,-0.5) 8(1.21,-0.5) 9(1.21,0) 10(1.21,0.5)
  rect 0.3x0.6 smd: 4(-0.75,-1.21) 5(-0.25,-1.21) 6(0.25,-1.21) 7(0.75,-1.21) 11(0.75,1.21) 12(0.25,1.21) 13(-0.25,1.21) 14(-0.75,1.21)
  rect 1.2x1.2 smd: 15(0,0)
XH2R54-4P-V
  rect 1.6x1.6 hole 1: 1(-3.75,0)
  round 1.6 hole 1: 2(-1.25,0) 3(1.25,0) 4(3.75,0)
ZH1P5MM_TH_2P
  round 1.05 hole 0.65: 1(-0.75,0) 2(0.75,0)

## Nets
1V05_AVDD_PHY: C83.1 C84.1 C85.1 C86.1 R107.2 U14.3(AVDD10_2) U14.8(AVDD10_1) U14.38(AVDD10)
1V05_DVDD_PHY: C79.1 C80.1 C81.1 C82.1 R106.1 U14.21(DVDD10)
1V05_PHY: C72.1 C73.1 L3.2 R106.2 R107.1
3V3_DVDD_PHY: C70.1 C71.1 C87.1 C88.1 C89.1 R80.1 R81.1 R82.1 R93.1 R94.1 R95.1 R104.2 R105.1 R240.1 U14.11(AVDD33_1) U14.28(DVDD_RG) U14.29(DVDD33) U14.40(AVDD33)
3V3_IMAGE0: C133.1 C138.1 J19.4 J19.5 R147.1 R151.1 U26.1(OUT)
3V3_IMAGE1: C134.1 C135.1 J20.4 J20.5 R149.1 R153.1 U27.1(OUT)
3V3_WLAN: C95.1 C96.1 Q6.3(DRAIN) U15.8(VCC3V3)
5V0_IMAGE0: C129.1 C130.1 J19.1 J19.2 J19.3 U25.1(OUT)
5V0_IMAGE1: C126.1 C127.1 J20.1 J20.2 J20.3 U24.1(OUT)
